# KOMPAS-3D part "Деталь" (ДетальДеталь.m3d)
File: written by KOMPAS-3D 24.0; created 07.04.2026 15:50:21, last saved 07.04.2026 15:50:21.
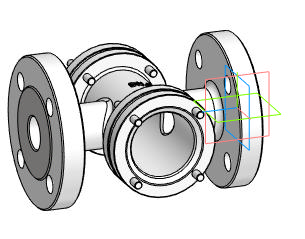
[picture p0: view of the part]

Document properties: Автор: Main; Полное имя файла: D:\DN.ru Аутсерс\Стекло смотровое DN.ru\Исходники\Стекло смотровое DN.ru SG2-34G-F тип В ГОСТ 21836-2021 Ду25 Ру40, углеродистая сталь, фланцевое\ДетальДеталь.m3d

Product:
- Body: Твердое тело1  | qty 1
- Part/product: Деталь
    additional columns: Типовые

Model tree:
1. Твердое тело1  (labels: Твердое тело1)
